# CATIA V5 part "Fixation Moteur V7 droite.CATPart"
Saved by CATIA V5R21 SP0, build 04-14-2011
Part number: MOTEURDROIT
Bounding box of the stored display mesh (mm): x -4.2 to 4.2, y -40 to 0, z -20 to 40
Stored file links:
  C:\Users\2027.DESARCY-LEMIE30\Desktop\V15(20.03.2023)\Fixation Moteur V7 droite.CATPart
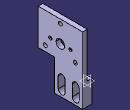
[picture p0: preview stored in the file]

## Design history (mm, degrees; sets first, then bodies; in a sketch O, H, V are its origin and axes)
Body1 (main body)
  Sketch1 on yz-plane, origin (0, 0, 0), H (0, 1, 0), V (0, 0, 1)
    line L1 (-40, 40) -> (0, 40)
    line L2 (0, 40) -> (0, 0)
    line L3 (0, 0) -> (-40, 0)
    line L4 (-40, 0) -> (-40, 40)
    point P3 (0, 0)
    length L4 = 40
    length L1 = 40
    horizontal: L1 H, L3 H
    vertical: L2 V, L4 V
    coincidence: P3 O
  Pad1: profile Sketch1, direction (1, 0, 0), length 4.2
  Sketch2 on end face of Pad1, origin (4.2, 0, 0), H (0, 1, 0), V (0, 0, 1)
    line L1 (-25, 0) -> (0, 0)
    line L2 (0, 0) -> (0, -20)
    line L3 (0, -20) -> (-25, -20)
    line L4 (-25, -20) -> (-25, 0)
    point P2 (0, 0)
    length L2 = 20
    length L3 = 25
    horizontal: L1 H, L3 H
    vertical: L2 V, L4 V
    coincidence: P2 O
  Pad2: profile Sketch2, direction (-1, 0, 0), length 8.4
  Sketch3 on end face of Pad2, origin (-4.2, 0, 0), H (0, -1, 0), V (0, 0, 1)
    point P1 (3.15, -5)
    line L1 (9.35, -5) -> (9.35, -15)
    line L2 (3.15, -15) -> (3.15, -5)
    point P2 (9.35, -5)
    point P3 (9.35, -15)
    point P4 (3.15, -15)
    axis line L3 (12.5, 2.3624) -> (12.5, -21.6714)
    reference projected line E1 (25, 0) -> (25, -20) from edge [end face of Pad2 | face of Pad2 from Sketch2.L4]
    arc A1 centre (6.25, -5) radius 3.1 from (9.35, -5) to (3.15, -5) ccw
    point P8 (10.7649, -15.4491)
    arc A2 centre (6.25, -15) radius 3.1 from (3.15, -15) to (9.35, -15) ccw
    point P9 (6.25, -15)
    point P10 (3.15, -15)
    point P11 (9.35, -15)
    point P12 (21.85, -5)
    point P13 (21.85, -15)
    line L4 (21.85, -15) -> (21.85, -5)
    point P14 (15.65, -5)
    arc A3 centre (18.75, -5) radius 3.1 from (15.65, -5) to (21.85, -5) cw
    point P16 (15.65, -15)
    line L5 (15.65, -5) -> (15.65, -15)
    point P17 (15.65, -15)
    point P18 (21.85, -15)
    point P19 (18.75, -15)
    arc A4 centre (18.75, -15) radius 3.1 from (21.85, -15) to (15.65, -15) cw
    reference projected line E2 (25, -20) -> (0, -20) from edge [end face of Pad2 | face of Pad2 from Sketch2.L3]
    distance L3 E1 = 12.5
    radius A1 = 3.1
    distance P9 P19 = 12.5
    length L4 = 10
    distance A4 E2 = 1.9
    vertical: L1 V, L2 V, L3 V
    tangency: A1 L1, A1 L2, A2 L1, A2 L2
    coincidence: P4 A2, L1 P11, L2 P10, P3 P11, P4 P10, P13 P18, P16 P17
    symmetry: P1 P12 L3, P4 P13 L3, L2 L4 L3, P2 P14 L3, A1 A3 L3, P3 P16 L3, L1 L5 L3, P11 P17 L3, P10 P18 L3, A2 A4 L3
  Pocket1: profile Sketch3, direction (1, 0, 0), through (limit type 3)
  Sketch4 on start face of Pad1, origin (0, 0, 0), H (0, -1, 0), V (0, 0, 1)
    construction line L1 (0, 20.75) -> (40, 20.75)
    point P1 (0, 20.75)
    point P2 (40, 20.75)
    reference projected line E1 (0, 40) -> (40, 40) from edge [start face of Pad1 | face of Pad1 from Sketch1.L1]
    reference projected line E2 (0, 0) -> (0, 40) from edge [start face of Pad1 | face of Pad2]
    reference projected line E3 (40, 40) -> (40, 0) from edge [start face of Pad1 | face of Pad1 from Sketch1.L4]
    construction line L2 (20, 40) -> (20, 0)
    point P3 (20, 40)
    point P4 (20, 0)
    reference projected line E4 (0, 40) -> (40, 40) from edge [start face of Pad1 | face of Pad1 from Sketch1.L1]
    reference projected line E5 (40, 0) -> (0, 0) from edge [start face of Pad1 | face of Pad1 from Sketch1.L3]
    reference projected line E6 (40, 40) -> (40, 0) from edge [start face of Pad1 | face of Pad1 from Sketch1.L4]
    circle A1 centre (20, 20.75) radius 4
    point P5 (20, 20.75)
    construction line L3 (20, 20.75) -> (0, 9.203)
    point P6 (0, 9.203)
    axis line L4 (20, 20.75) -> (40, 9.203)
    point P7 (40, 9.203)
    reference projected line E7 (40, 40) -> (40, 0) from edge [start face of Pad1 | face of Pad1 from Sketch1.L4]
    circle A2 centre (20, 36.3385) radius 1.75
    point P8 (20, 36.3385)
    point P9 (33.5, 12.9558)
    circle A3 centre (33.5, 12.9558) radius 1.75
    point P10 (6.5, 12.9558)
    circle A4 centre (6.5, 12.9558) radius 1.75
    distance E1 L1 = 19.25
    distance L2 E6 = 20
    radius A1 = 4
    angle L3 L2 = 120
    angle L2 L4 = 120
    radius A2 = 1.75
    distance P9 P10 = 27
    coincidence: P1 E2, P2 E3, E4 P3, P4 E5, P6 V, P7 E7, P8 L2, P5 L1, P5 L2
    vertical: L2 V
    symmetry: A2 A3 L3, A3 A4 L2
  Pocket2: profile Sketch4, direction (1, 0, 0), through (limit type 3)
  Sketch5 on start face of Pad1, origin (0, 0, 0), H (0, -1, 0), V (0, 0, 1)
    point P1 (40, 0)
    line L1 (40, 0) -> (25, 0)
    line L2 (25, 0) -> (25, 8)
    line L3 (25, 8) -> (40, 8)
    line L4 (40, 8) -> (40, 0)
    reference projected line E1 (0, -20) -> (0, 0) from edge [end face of Pad2 | face of Pad2 from Sketch2.L2]
    reference projected line E2 (25, 0) -> (25, -20) from edge [end face of Pad2 | face of Pad2 from Sketch2.L4]
    reference projected point E3 (40, 0) from vertex [face of Pad1 from Sketch1.L3 | start face of Pad1 | face of Pad1 from Sketch1.L4]
    length L2 = 8
    length L3 = 15
    distance E1 E2 = 25 (reference)
    horizontal: L1 H, L3 H
    vertical: L2 V, L4 V
    coincidence: P1 E3
  Pocket3: profile Sketch5, direction (1, 0, 0), through (limit type 3)
  Sketch6 on start face of Pad1, origin (0, -33.8289, 21.1001), H (0, 1, 0), V (0, 0, -1)
    point P1 (22.8289, 0.3501)
    axis line L1 (13.8289, 0.3501) -> (40.6944, 0.3501)
    point P2 (13.8289, 0.3501)
    reference projected circle E1 centre (13.8289, 0.3501) radius 4 from edge [start face of Pad1 | face of Pocket2 from Sketch4.A1]
    reference projected circle E2 centre (13.8289, 0.3501) radius 4 from edge [start face of Pad1 | face of Pocket2 from Sketch4.A1]
    distance P1 E2 = 5
    horizontal: L1 H
    concentricity: P2 E1
    coincidence: P1 L1
  Hole1: placed by Sketch6, at (0, -11, 20.75) direction (1, 0, 0), diameter 3, through (limit type 6), counterbore diameter 6, counterbore depth 3
  RectPattern1: of Hole1, direction 1 instances 2, spacing 18, along face of Pad1 from Sketch1.L1 reversed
